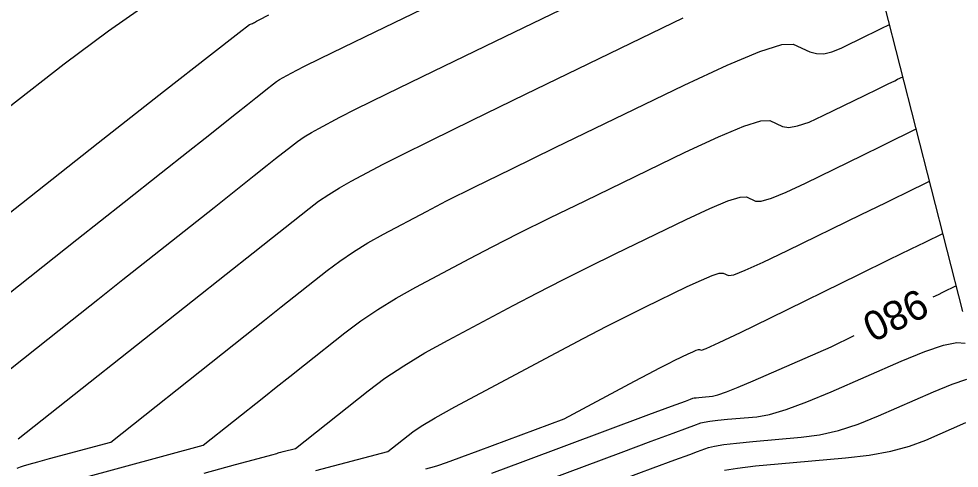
# Model space of a CAD drawing. Extents: x 2175772 to 2185556, y 721391 to 722853.
# Drawn here: x 2179071.3 to 2179161.1, y 721977.4 to 722020.3 of the extents above; entities that cross this region are included whole.
import ezdxf

# ---------------------------------------------------------------- set-up
doc = ezdxf.new("R2010")
doc.units = 0
for name, color, linetype in [('DT_X_Contour_Major', 7, 'Continuous'), ('DT_X_Contour_Minor', 7, 'Continuous'), ('DT_X_TIN_Hull', 7, 'Continuous')]:
    doc.layers.add(name, color=color, linetype=linetype)

msp = doc.modelspace()

# ---------------------------------------------------------------- linework, layer by layer
at = {"layer": 'DT_X_Contour_Major'}
for points in [[(2179057.809, 722002.053), (2179070.246, 722011.852), (2179075.635, 722016.04), (2179079.863, 722019.198), (2179082.93, 722021.325), (2179084.835, 722022.421), (2179088.367, 722023.97), (2179089.669, 722024.559), (2179090.927, 722025.166), (2179092.141, 722025.789), (2179093.311, 722026.43), (2179096.371, 722028.161), (2179098.074, 722029.08), (2179100.89, 722030.539), (2179104.817, 722032.538), (2179109.857, 722035.077), (2179124.779, 722042.567), (2179129.865, 722045.062), (2179133.933, 722046.93), (2179136.982, 722048.17), (2179139.013, 722048.783), (2179146.111, 722050.178)], [(2179071.13, 721977.441), (2179071.471, 721977.564), (2179071.74, 721977.646), (2179072.289, 721977.802), (2179073.119, 721978.031), (2179074.231, 721978.334), (2179080.072, 721979.917), (2179090.758, 721988.389), (2179092.906, 721990.092), (2179094.77, 721991.57), (2179096.352, 721992.824), (2179100.734, 721996.298), (2179101.938, 721997.202), (2179103.237, 721998.082), (2179104.631, 721998.937), (2179106.121, 721999.767), (2179110.221, 722001.948), (2179112.143, 722002.943), (2179114.833, 722004.292), (2179118.291, 722005.994), (2179122.518, 722008.05), (2179134.815, 722014.005), (2179138.924, 722015.925), (2179142.028, 722017.219), (2179144.128, 722017.886), (2179145.224, 722017.927), (2179146.807, 722017.2), (2179147.439, 722017.016), (2179148.147, 722017.011), (2179148.931, 722017.183), (2179149.792, 722017.534), (2179152.189, 722018.707), (2179152.983, 722019.096), (2179153.57, 722019.383), (2179153.948, 722019.568), (2179154.117, 722019.651), (2179154.422, 722019.8)], [(2179158.591, 721993.783), (2179159.085, 721994.025), (2179159.516, 721994.236), (2179160.802, 721994.866)], [(2179116.453, 721976.959), (2179119.446, 721978.073), (2179131.457, 721982.543), (2179133.607, 721983.342), (2179134.93, 721983.834), (2179135.427, 721984.018), (2179135.65, 721984.098), (2179135.768, 721984.128), (2179135.957, 721984.158), (2179136.215, 721984.19), (2179136.543, 721984.221), (2179137.511, 721984.307), (2179138.027, 721984.422), (2179138.851, 721984.703), (2179139.981, 721985.15), (2179141.419, 721985.763), (2179148.844, 721989.013), (2179151.046, 721990.091)]]:
    msp.add_lwpolyline(points, dxfattribs=at)
at = {"layer": 'DT_X_Contour_Minor'}
for points in [[(2179062.425, 721980.518), (2179076.408, 721991.603), (2179078.84, 721993.531), (2179081.247, 721995.439), (2179083.628, 721997.328), (2179089.946, 722002.336), (2179093.782, 722005.378), (2179095.024, 722006.362), (2179095.815, 722006.989), (2179097.323, 722008.184), (2179097.911, 722008.627), (2179098.546, 722009.057), (2179099.228, 722009.475), (2179099.956, 722009.88), (2179101.961, 722010.947), (2179103.453, 722011.701), (2179106.426, 722013.163), (2179110.88, 722015.334), (2179116.816, 722018.213), (2179134.618, 722026.834)], [(2179053.602, 721980.818), (2179076.855, 721999.253), (2179081.356, 722002.821), (2179084.894, 722005.626), (2179087.469, 722007.668), (2179089.081, 722008.946), (2179092.097, 722011.337), (2179093.12, 722012.148), (2179093.928, 722012.788), (2179094.52, 722013.258), (2179094.898, 722013.557), (2179095.617, 722014.128), (2179095.898, 722014.339), (2179096.201, 722014.544), (2179096.527, 722014.743), (2179096.874, 722014.937), (2179097.831, 722015.446), (2179098.568, 722015.818), (2179100.061, 722016.552), (2179102.312, 722017.648), (2179105.319, 722019.107), (2179114.346, 722023.479)], [(2179059.929, 721993.549), (2179078.889, 722008.487), (2179085.124, 722013.394), (2179089.608, 722016.913), (2179092.34, 722019.043), (2179093.322, 722019.783), (2179093.604, 722019.907), (2179093.709, 722019.955), (2179093.809, 722020.003), (2179093.906, 722020.053), (2179094, 722020.104), (2179094.245, 722020.243), (2179095.183, 722020.719)], [(2179071.249, 721980.218), (2179087.882, 721993.405), (2179091.109, 721995.962), (2179093.659, 721997.984), (2179095.534, 721999.471), (2179096.732, 722000.421), (2179099.028, 722002.241), (2179099.924, 722002.914), (2179100.892, 722003.569), (2179101.93, 722004.206), (2179103.039, 722004.824), (2179106.091, 722006.447), (2179107.798, 722007.322), (2179110.629, 722008.727), (2179114.586, 722010.664), (2179119.667, 722013.132), (2179134.716, 722020.42)], [(2179077.312, 721976.477), (2179088.895, 721979.617), (2179094.703, 721984.221), (2179095.882, 721985.156), (2179097.17, 721986.177), (2179098.567, 721987.285), (2179102.439, 721990.354), (2179103.951, 721991.49), (2179105.582, 721992.594), (2179107.333, 721993.668), (2179109.203, 721994.71), (2179114.351, 721997.449), (2179116.487, 721998.564), (2179119.036, 721999.856), (2179121.996, 722001.324), (2179125.369, 722002.969), (2179134.913, 722007.591), (2179138.102, 722009.081), (2179140.511, 722010.085), (2179142.141, 722010.603), (2179142.992, 722010.634), (2179144.221, 722010.07), (2179144.808, 722009.975), (2179145.65, 722010.114), (2179146.745, 722010.486), (2179148.094, 722011.092), (2179152.03, 722013.018), (2179153.335, 722013.657), (2179154.298, 722014.128), (2179154.918, 722014.432), (2179155.197, 722014.568), (2179155.698, 722014.813)], [(2179088.994, 721976.952), (2179092.003, 721977.768), (2179094.16, 721978.353), (2179095.466, 721978.709), (2179095.92, 721978.834), (2179095.996, 721978.861), (2179096.052, 721978.878), (2179096.164, 721978.909), (2179096.331, 721978.954), (2179096.553, 721979.012), (2179097.719, 721979.317), (2179104.663, 721984.822), (2179106.256, 721986.009), (2179108.057, 721987.21), (2179110.067, 721988.425), (2179112.286, 721989.654), (2179118.481, 721992.949), (2179120.832, 721994.185), (2179123.239, 721995.42), (2179125.702, 721996.654), (2179128.22, 721997.888), (2179135.011, 722001.177), (2179137.28, 722002.237), (2179138.995, 722002.951), (2179140.154, 722003.32), (2179140.76, 722003.342), (2179141.634, 722002.94), (2179142.177, 722002.934), (2179143.152, 722003.217), (2179144.558, 722003.789), (2179146.396, 722004.649), (2179151.871, 722007.329), (2179153.687, 722008.217), (2179155.026, 722008.873), (2179155.889, 722009.295), (2179156.277, 722009.485), (2179156.974, 722009.826)], [(2179099.646, 721977.215), (2179106.542, 721979.016), (2179108.918, 721980.9), (2179109.703, 721981.433), (2179111.039, 721982.228), (2179112.928, 721983.282), (2179115.368, 721984.597), (2179122.611, 721988.45), (2179125.177, 721989.806), (2179127.442, 721990.984), (2179129.407, 721991.984), (2179131.072, 721992.807), (2179135.109, 721994.762), (2179136.458, 721995.393), (2179137.478, 721995.817), (2179138.167, 721996.036), (2179138.527, 721996.05), (2179139.047, 721995.811), (2179139.546, 721995.894), (2179140.655, 721996.32), (2179142.372, 721997.091), (2179144.698, 721998.207), (2179151.712, 722001.64), (2179154.038, 722002.778), (2179156.86, 722004.159), (2179157.356, 722004.402), (2179158.25, 722004.839)], [(2179110.147, 721977.357), (2179110.97, 721977.576), (2179111.292, 721977.666), (2179111.485, 721977.735), (2179112.473, 721978.101), (2179113.6, 721978.52), (2179115.149, 721979.097), (2179123.361, 721982.153), (2179130.08, 721985.727), (2179131.4, 721986.426), (2179132.48, 721986.993), (2179133.321, 721987.426), (2179133.923, 721987.726), (2179135.207, 721988.348), (2179135.637, 721988.548), (2179135.961, 721988.683), (2179136.18, 721988.753), (2179136.295, 721988.757), (2179136.46, 721988.681), (2179136.916, 721988.853), (2179138.157, 721989.424), (2179140.185, 721990.394), (2179143, 721991.764), (2179151.554, 721995.951), (2179154.39, 721997.339), (2179156.482, 721998.363), (2179157.831, 721999.023), (2179159.526, 721999.853)], [(2179120.177, 721975.722), (2179128.802, 721978.932), (2179131.662, 721979.996), (2179133.773, 721980.78), (2179135.137, 721981.285), (2179135.752, 721981.511), (2179136.394, 721981.741), (2179136.735, 721981.828), (2179137.276, 721981.916), (2179138.019, 721982.006), (2179138.962, 721982.097), (2179141.744, 721982.343), (2179142.971, 721982.561), (2179144.564, 721983.03), (2179146.524, 721983.751), (2179148.85, 721984.723), (2179155.541, 721987.652), (2179157.806, 721988.583), (2179159.58, 721989.178), (2179160.864, 721989.439), (2179161.658, 721989.364)], [(2179129.121, 721976.428), (2179131.866, 721977.448), (2179133.94, 721978.218), (2179135.344, 721978.737), (2179136.077, 721979.005), (2179137.137, 721979.385), (2179137.701, 721979.528), (2179138.596, 721979.674), (2179139.822, 721979.823), (2179141.381, 721979.973), (2179145.978, 721980.379), (2179147.733, 721980.62), (2179149.55, 721981.038), (2179151.429, 721981.635), (2179153.371, 721982.409), (2179158.632, 721984.712), (2179160.412, 721985.444), (2179161.807, 721985.912)], [(2179138.667, 721977.228), (2179139.915, 721977.432), (2179141.626, 721977.639), (2179143.799, 721977.849), (2179150.211, 721978.415), (2179152.494, 721978.679), (2179154.536, 721979.047), (2179156.335, 721979.519), (2179157.892, 721980.096), (2179161.723, 721981.772)]]:
    msp.add_lwpolyline(points, dxfattribs=at)
at = {"layer": 'DT_X_TIN_Hull'}
msp.add_lwpolyline([(2179161.432, 721992.402), (2179152.436, 722027.565), (2179148.143, 722033.953), (2179145.688, 722053.555), (2179140.977, 722068.944), (2179128.836, 722075.112), (2179107.616, 722089.392), (2179075.122, 722109.69)], dxfattribs=at)

# ---------------------------------------------------------------- texts
at = {"layer": 'DT_X_Contour_Major'}
msp.add_text('980', height=2.8, rotation=206.0781, dxfattribs=at).set_placement((2179157.193, 721994.658))

doc.saveas('drawing.dxf')
